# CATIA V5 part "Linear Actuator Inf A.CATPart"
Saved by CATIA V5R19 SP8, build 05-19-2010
Part number: Linear Actuator Inf A
Bounding box of the stored display mesh (mm): x -24.865 to 24.865, y 0 to 120, z 595.003 to 644.997
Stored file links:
  G:\EU_thinkMotion\CFAO_2010\MMS_groupe3\MMS_groupe3\A reprendre\fovide\fovide\Linear Actuator Inf A.CATPart
  G:\EU_thinkMotion\CFAO_2010\MMS_groupe3\MMS_groupe3\A reprendre\fovide\fovide\fovide.CATProduct
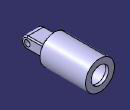
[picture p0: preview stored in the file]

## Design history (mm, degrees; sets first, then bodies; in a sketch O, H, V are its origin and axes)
Set1
  Plane1: linked copy from another document
  Point1 "Point.O": linked copy from another document
  Line1: linked copy from another document
  Line2: linked copy from another document
Body1 (main body)
  Sketch1 on Plane1, origin (0, 0, 0), H (0, 1, 0), V (0, 0, 1)
    arc A1 centre (10, 620) radius 10 from (10, 630) to (10.0485, 610.0001) ccw
    point P1 (10, 620)
    reference projected point E1 (10, 620) from Point1
    line L1 (10, 630) -> (40, 630)
    line L2 (40, 630) -> (40, 610.0001)
    line L3 (40, 610.0001) -> (10.0485, 610.0001)
    length L1 = 30
    radius A1 = 10
    coincidence: P1 E1
    tangency: L1 A1
    vertical: L2 V
    horizontal: L1 H, L3 H
  Pad1: profile Sketch1, direction (1, 0, 0), length 15, mirrored extent
  Sketch2 on Plane1, origin (0, 0, 0), H (0, 1, 0), V (0, 0, 1)
    line L1 (40, 620) -> (40, 645)
    line L2 (40, 645) -> (120, 645)
    line L3 (120, 645) -> (120, 635)
    line L4 (120, 635) -> (115, 635)
    line L5 (115, 635) -> (115, 640)
    line L6 (115, 640) -> (45, 640)
    line L7 (45, 640) -> (45, 620)
    line L8 (45, 620) -> (40, 620)
    reference projected line E1 (40, 610.0001) -> (40, 630) from edge [face of Pad1 from Sketch1.L2 | end face of Pad1]
    reference projected line E2 (410, 620) -> (10, 620) from Line1
    length L1 = 25
    length L3 = 10
    length L4 = 5
    length L5 = 5
    distance L7 L1 = 5
    length L2 = 80
    vertical: L1 V, L3 V, L5 V, L7 V
    horizontal: L2 H, L4 H, L6 H, L8 H
    coincidence: L1 E1, L8 E2
  Shaft1: profile Sketch2, axis Line1, angle 360
  Fillet1: radius 2, on face of Shaft1 from Sketch2.L1; end face of Pad1; start face of Pad1
  Sketch3 on end face of Pad1, origin (15, 10, 620), H (0, 1, 0), V (0, 0, 1)
    point P1 (0, 0)
    intersected point E1 (0, 0) from Line2
    coincidence: E1 P1
  Hole1: placed by Sketch3, at (15, 10, 620) direction (-1, 0, 0), diameter 10, through (limit type 3)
